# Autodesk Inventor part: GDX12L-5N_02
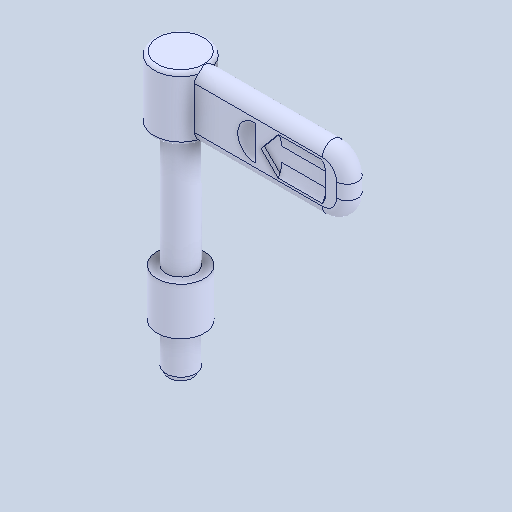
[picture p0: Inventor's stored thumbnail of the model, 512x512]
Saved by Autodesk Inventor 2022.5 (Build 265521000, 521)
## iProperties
Created: 2024-06
Part Number: GDX12L-5N_02
Material: 一般
Document SubType Name: Modeling
Designer: ImaoCorp
Density: 1 g/cm^3
Appearance: 既定
Author: ImaoCorp
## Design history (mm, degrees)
feature "GDX12L-5N_02"
node "ソリッド1"
